Omron CX-Programmer project NuevoProyecto (CX-Programmer 9.51)

# PLC NuevoPLC1: CP1L-E EM

## Global symbols (name address type ; comment)
102.07 BOOL  ; Permis  aspiracio fiser127_8
10.05 BOOL  ; A
220.00 BOOL  ; Alarma 0
220.14 BOOL  ; Alarma batten aspirador
220.15 BOOL  ; Alarma fiser 127_15 aspirador
221.00 BOOL  ; Alarma Fise 127_08 aspirador
T0015 BOOL  ; Temps Acustic per Emmergència
W0.00 BOOL  ; Automatic inici validat
W0.01 BOOL  ; AuxSacBuit
W10.00 BOOL  ; AutomAspirarBatten
W10.01 BOOL  ; AutoAspirarFiser
W10.05 BOOL  ; AutoVibrador
PesApr1500Control D400 CHANNEL  ; d20
PesApr1500ControlXm D401 CHANNEL  ; Celula carga APR  canal de control
PesApr1500ControlY0 D402 CHANNEL  ; Celula carga APR  canal de control
PesApr1500ControlY1 D403 CHANNEL  ; Celula carga APR  canal de control
ScrPesActual D20 INT  ; Valor per la pantalla del pes
ScrPesTarat D22 INT  ; Valor del pes ja tarat
ScrValorMaxPes D24 INT
ScrValorMinPes D23 INT
ScrValorTarat D21 INT  ; Valorque restem al pes real i el passem al tarat
bAutoBattenAigua W10.07 BOOL
bAutoBattenEvAtemp W10.08 BOOL
bAutoBattenEvOli W10.06 BOOL
bAutoFiser127_8Aspir W11.00 BOOL  ; Permis  aspiracio fiser 127_8
bAutoFiserEvAigua W10.10 BOOL
bAutoFiserEvAtemp W10.11 BOOL
bAutoFiserEvOli W10.09 BOOL
bAutoPotRefrigAigua W10.13 BOOL
bAutoPotRefrigAtemp W10.14 BOOL
bAutoPotRefrigOli W10.12 BOOL
bHabBattenEvAigua H8.01 BOOL
bHabBattenEvAtemperador H8.02 BOOL
bHabBattenEvOli H8.00 BOOL
bHabFiserEvAigua H8.04 BOOL
bHabFiserEvAtemperador H8.05 BOOL
bHabFiserEvOli H8.03 BOOL
bHabpotRefrigAigua H8.07 BOOL
bHabpotRefrigAtemp H8.08 BOOL
bHabpotRefrigOli H8.06 BOOL
bManBattenAspir H10.00 BOOL  ; Permis  aspiracio batten
bManBattenEvAigua H10.07 BOOL
bManBattenEvAtemp H10.08 BOOL
bManBattenEvOli H10.06 BOOL
bManFiser127_8Aspir H11.00 BOOL  ; Permis  aspiracio fiser 127_8
bManFiserEvAigua H10.10 BOOL
bManFiserEvAtemp H10.11 BOOL
bManFiserEvOli H10.09 BOOL
bManGranzaVibrador H10.15 BOOL
bManPolsEvBatten127_09 H10.04 BOOL
bManPolsEvFiser127_08 H10.02 BOOL
bManPolsEvFiser127_15 H10.03 BOOL
bManPotRefrigAigua H10.13 BOOL
bManPotRefrigAtemp H10.14 BOOL
bManPotRefrigOli H10.12 BOOL
bManrFiserAspir H10.01 BOOL  ; Permis  aspiracio fiser
bScrBattenAspir 200.00 BOOL  ; Permis  aspiracio batten
bScrBattenEvAigua 200.07 BOOL
bScrBattenEvAtemp 200.08 BOOL
bScrBattenEvOli 200.06 BOOL
bScrFiserAspir 200.01 BOOL  ; Permis  aspiracio fiser
bScrFiserEvAigua 200.10 BOOL
bScrFiserEvAtemp 200.11 BOOL
bScrFiserEvOli 200.09 BOOL
bScrGranzaBaixa 200.05 BOOL
bScrGranzaPujar 200.04 BOOL
bScrGranzaVibrador 200.15 BOOL
bScrPolsEvBatten127_09 203.01 BOOL
bScrPolsEvFiser127_08 200.02 BOOL
bScrPolsEvFiser127_15 200.03 BOOL
bScrPotRefrigAigua 200.13 BOOL
bScrPotRefrigAtemp 200.14 BOOL
bScrPotRefrigOli 200.12 BOOL
inBarrera 1.02 BOOL
inBattenOn 1.00 BOOL
inDetFinalSac 0.06 BOOL
inDetIniciSac 0.07 BOOL
inEVGFiser127_15Tancat 0.03 BOOL
inEmergencia 1.03 BOOL
inEvBatten127_09Obert 1.05 BOOL
inEvBatten127_09Tancat 1.06 BOOL
inEvFiser127_08Obert 0.00 BOOL
inEvFiser127_08Tancat 0.01 BOOL
inEvFiser127_15Obert 0.02 BOOL
inFiserOn 1.01 BOOL
inNivellAspBatten 0.04 BOOL  ; Batten
inNivellAspFiser127_15 0.05 BOOL  ; Fiser
inNivellAspFiser127_8 1.04 BOOL  ; Fiser 127-8
inPolsBaixar 0.10 BOOL
inPolsPujar 0.09 BOOL
inPolsValidarInici 0.11 BOOL
inSelManAuto 0.08 BOOL  ; 0:Auto  1:Man
outBalisa 102.04 BOOL
outBattenAspir 100.00 BOOL  ; Permis  aspiracio batten
outBattenEvAigua 100.07 BOOL
outBattenEvAtemp 101.00 BOOL
outBattenEvOli 100.06 BOOL
outEVGBatten 100.04 BOOL  ; Batten
outEVGFiser127_15 100.05 BOOL  ; Fiser
outEvFiser127_08 102.06 BOOL  ; Fiser 127_8
outFiserAspir 100.01 BOOL  ; Permis  aspiracio fiser
outFiserEvAigua 101.02 BOOL
outFiserEvAtemp 101.03 BOOL
outFiserEvOli 101.01 BOOL
outGranzaBaixa 100.03 BOOL  ; Per baixar el soport del sac hem de fer sortir el pisto
outGranzaPujar 100.02 BOOL  ; per mantenir el sac tensat hem de fer entrar el pisto
outGranzaVibrador 101.07 BOOL
outPotRefrigAigua 101.05 BOOL
outPotRefrigAtemp 101.06 BOOL
outPotRefrigOli 101.04 BOOL
outSemaforGroc 102.01 BOOL
outSemaforSirena 102.03 BOOL
outSemaforVerd 102.00 BOOL
outSemaforVermell 102.02 BOOL
outValidarIniciLed 102.05 BOOL
scrAlarmaDiplay W0.03 BOOL
scrCanviPantalla D11 INT  ; Numero de pantalla a la que es vol anar
scrCanviPantallaComando D10 INT  ; El numero 2 vol dir escriure
scrIconaAlarma W0.02 BOOL
scrPolsTarar 203.00 BOOL

## Program NuevoPrograma1 (cyclic task 0)
Local symbols
f113 BOOL

### Section Manual

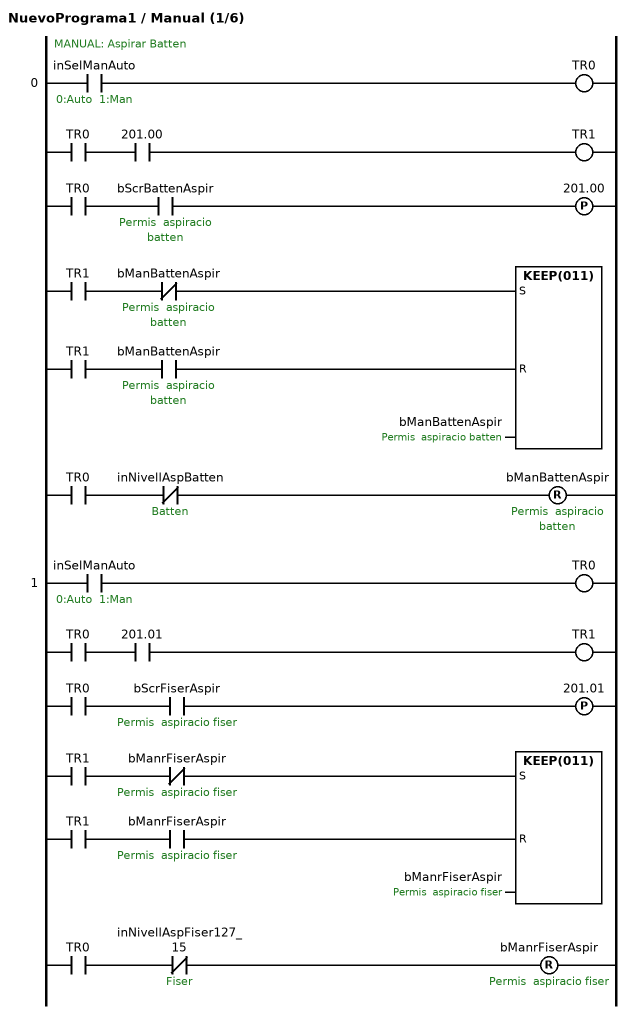
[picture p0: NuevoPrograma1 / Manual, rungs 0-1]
; rung 0: MANUAL: Aspirar Batten
LD inSelManAuto  ; 0:Auto  1:Man
OUT TR0
AND bScrBattenAspir  ; Permis  aspiracio batten
DIFU(013) 201.00
LD TR0
AND 201.00
OUT TR1
ANDNOT bManBattenAspir  ; Permis  aspiracio batten
LD TR1
AND bManBattenAspir  ; Permis  aspiracio batten
KEEP(011) bManBattenAspir  ; Permis  aspiracio batten
LD TR0
ANDNOT inNivellAspBatten  ; Batten
RSET bManBattenAspir  ; Permis  aspiracio batten
; rung 1
LD inSelManAuto  ; 0:Auto  1:Man
OUT TR0
AND bScrFiserAspir  ; Permis  aspiracio fiser
DIFU(013) 201.01
LD TR0
AND 201.01
OUT TR1
ANDNOT bManrFiserAspir  ; Permis  aspiracio fiser
LD TR1
AND bManrFiserAspir  ; Permis  aspiracio fiser
KEEP(011) bManrFiserAspir  ; Permis  aspiracio fiser
LD TR0
ANDNOT inNivellAspFiser127_15  ; Fiser
RSET bManrFiserAspir  ; Permis  aspiracio fiser

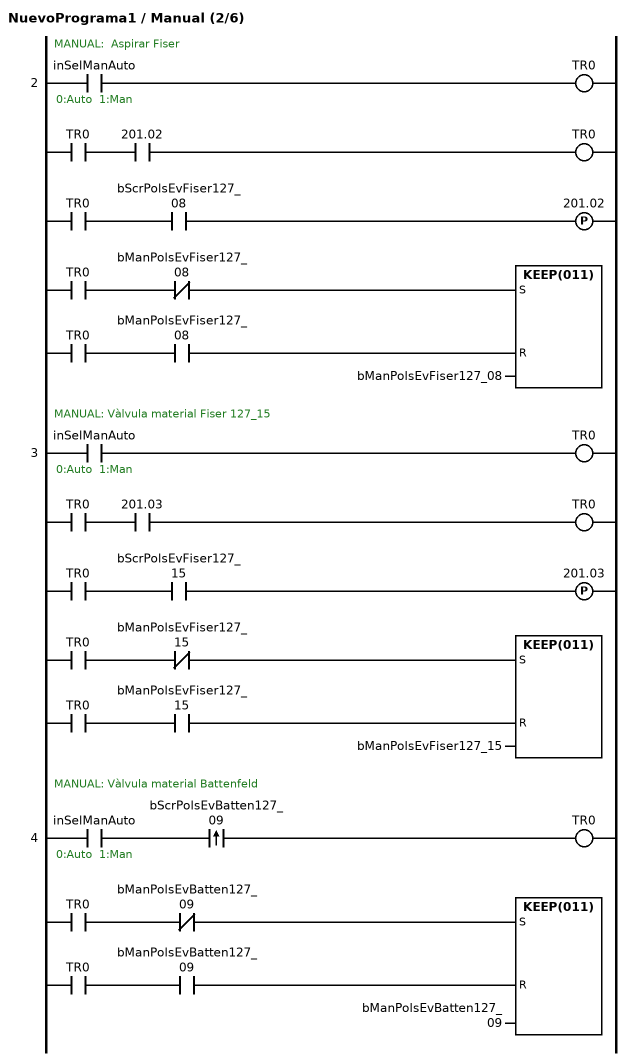
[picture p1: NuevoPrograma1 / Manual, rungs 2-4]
; rung 2: MANUAL:  Aspirar Fiser
LD inSelManAuto  ; 0:Auto  1:Man
OUT TR0
AND bScrPolsEvFiser127_08
DIFU(013) 201.02
LD TR0
AND 201.02
OUT TR0
ANDNOT bManPolsEvFiser127_08
LD TR0
AND bManPolsEvFiser127_08
KEEP(011) bManPolsEvFiser127_08
; rung 3: MANUAL: Vàlvula material Fiser 127_15
LD inSelManAuto  ; 0:Auto  1:Man
OUT TR0
AND bScrPolsEvFiser127_15
DIFU(013) 201.03
LD TR0
AND 201.03
OUT TR0
ANDNOT bManPolsEvFiser127_15
LD TR0
AND bManPolsEvFiser127_15
KEEP(011) bManPolsEvFiser127_15
; rung 4: MANUAL: Vàlvula material Battenfeld
LD inSelManAuto  ; 0:Auto  1:Man
@AND bScrPolsEvBatten127_09
OUT TR0
ANDNOT bManPolsEvBatten127_09
LD TR0
AND bManPolsEvBatten127_09
KEEP(011) bManPolsEvBatten127_09

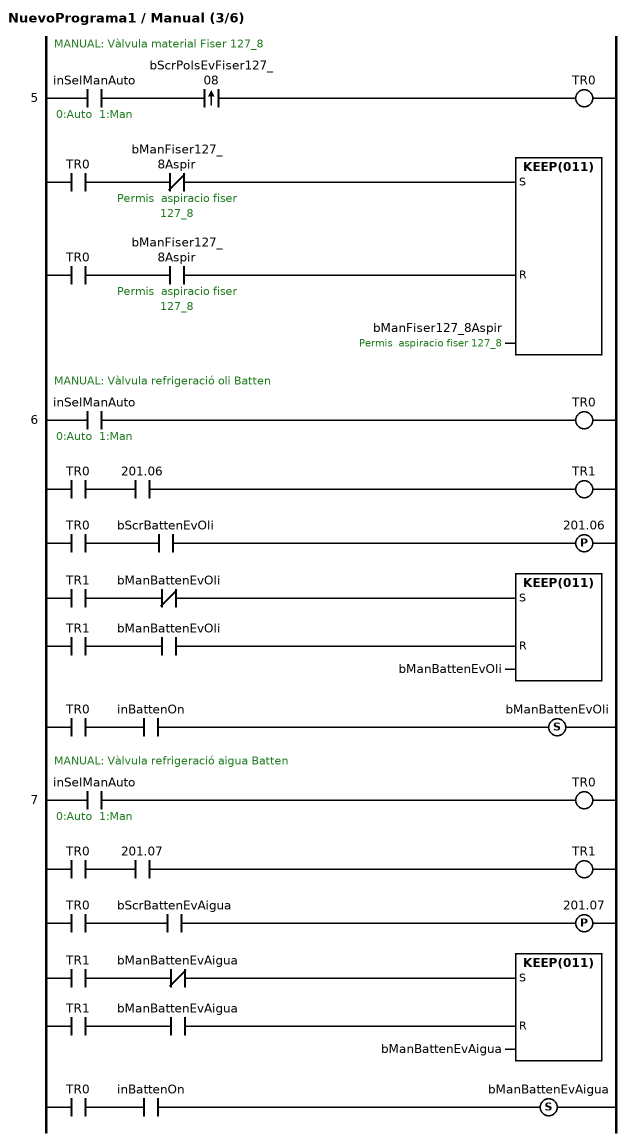
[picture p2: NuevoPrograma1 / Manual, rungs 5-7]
; rung 5: MANUAL: Vàlvula material Fiser 127_8
LD inSelManAuto  ; 0:Auto  1:Man
@AND bScrPolsEvFiser127_08
OUT TR0
ANDNOT bManFiser127_8Aspir  ; Permis  aspiracio fiser 127_8
LD TR0
AND bManFiser127_8Aspir  ; Permis  aspiracio fiser 127_8
KEEP(011) bManFiser127_8Aspir  ; Permis  aspiracio fiser 127_8
; rung 6: MANUAL: Vàlvula refrigeració oli Batten
LD inSelManAuto  ; 0:Auto  1:Man
OUT TR0
AND bScrBattenEvOli
DIFU(013) 201.06
LD TR0
AND 201.06
OUT TR1
ANDNOT bManBattenEvOli
LD TR1
AND bManBattenEvOli
KEEP(011) bManBattenEvOli
LD TR0
AND inBattenOn
SET bManBattenEvOli
; rung 7: MANUAL: Vàlvula refrigeració aigua Batten
LD inSelManAuto  ; 0:Auto  1:Man
OUT TR0
AND bScrBattenEvAigua
DIFU(013) 201.07
LD TR0
AND 201.07
OUT TR1
ANDNOT bManBattenEvAigua
LD TR1
AND bManBattenEvAigua
KEEP(011) bManBattenEvAigua
LD TR0
AND inBattenOn
SET bManBattenEvAigua

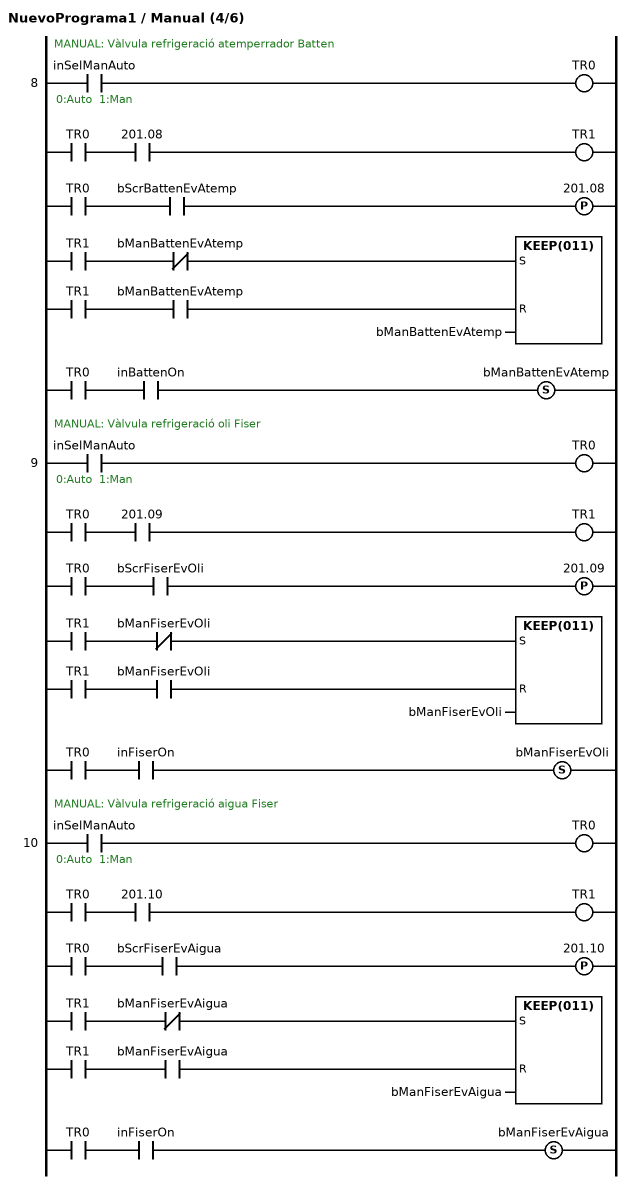
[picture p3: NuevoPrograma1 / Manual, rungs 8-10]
; rung 8: MANUAL: Vàlvula refrigeració atemperrador Batten
LD inSelManAuto  ; 0:Auto  1:Man
OUT TR0
AND bScrBattenEvAtemp
DIFU(013) 201.08
LD TR0
AND 201.08
OUT TR1
ANDNOT bManBattenEvAtemp
LD TR1
AND bManBattenEvAtemp
KEEP(011) bManBattenEvAtemp
LD TR0
AND inBattenOn
SET bManBattenEvAtemp
; rung 9: MANUAL: Vàlvula refrigeració oli Fiser
LD inSelManAuto  ; 0:Auto  1:Man
OUT TR0
AND bScrFiserEvOli
DIFU(013) 201.09
LD TR0
AND 201.09
OUT TR1
ANDNOT bManFiserEvOli
LD TR1
AND bManFiserEvOli
KEEP(011) bManFiserEvOli
LD TR0
AND inFiserOn
SET bManFiserEvOli
; rung 10: MANUAL: Vàlvula refrigeració aigua Fiser
LD inSelManAuto  ; 0:Auto  1:Man
OUT TR0
AND bScrFiserEvAigua
DIFU(013) 201.10
LD TR0
AND 201.10
OUT TR1
ANDNOT bManFiserEvAigua
LD TR1
AND bManFiserEvAigua
KEEP(011) bManFiserEvAigua
LD TR0
AND inFiserOn
SET bManFiserEvAigua

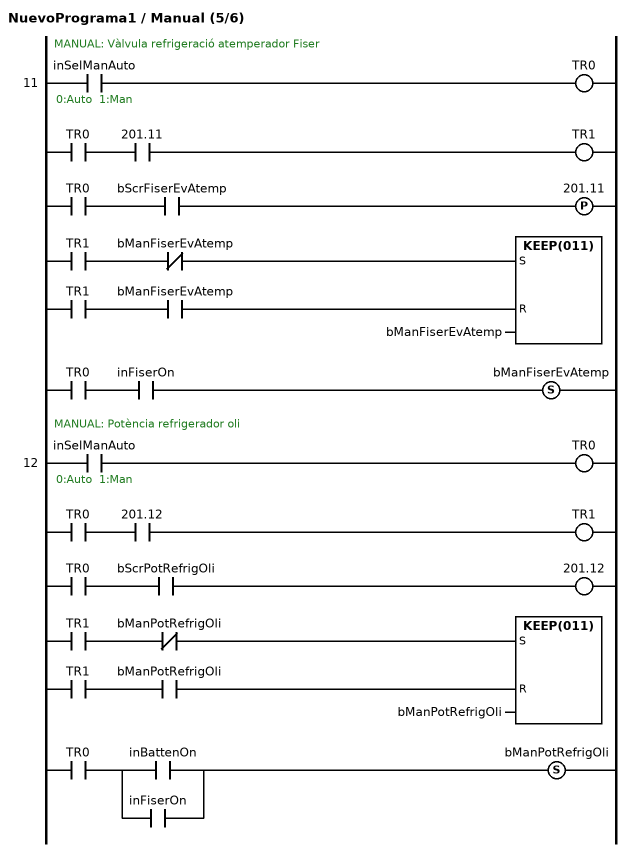
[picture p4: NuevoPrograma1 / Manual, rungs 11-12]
; rung 11: MANUAL: Vàlvula refrigeració atemperador Fiser
LD inSelManAuto  ; 0:Auto  1:Man
OUT TR0
AND bScrFiserEvAtemp
DIFU(013) 201.11
LD TR0
AND 201.11
OUT TR1
ANDNOT bManFiserEvAtemp
LD TR1
AND bManFiserEvAtemp
KEEP(011) bManFiserEvAtemp
LD TR0
AND inFiserOn
SET bManFiserEvAtemp
; rung 12: MANUAL: Potència refrigerador oli
LD inSelManAuto  ; 0:Auto  1:Man
OUT TR0
AND bScrPotRefrigOli
OUT 201.12
LD TR0
AND 201.12
OUT TR1
ANDNOT bManPotRefrigOli
LD TR1
AND bManPotRefrigOli
KEEP(011) bManPotRefrigOli
LD TR0
LD inBattenOn
OR inFiserOn
ANDLD
SET bManPotRefrigOli

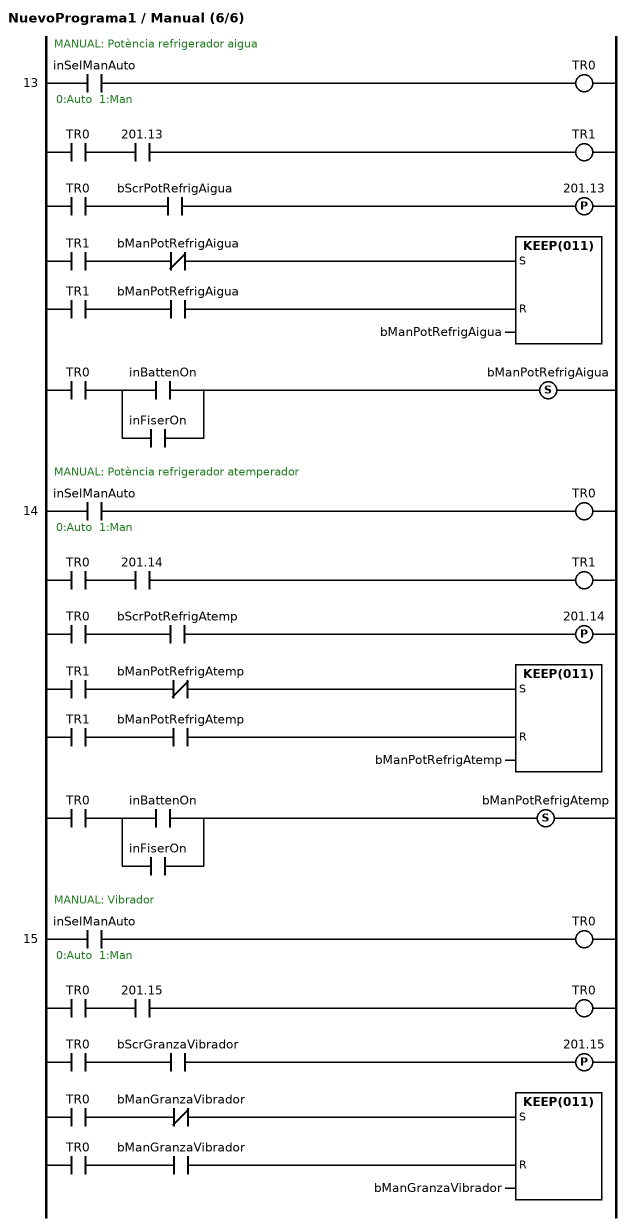
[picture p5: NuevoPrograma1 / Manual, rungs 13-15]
; rung 13: MANUAL: Potència refrigerador aigua
LD inSelManAuto  ; 0:Auto  1:Man
OUT TR0
AND bScrPotRefrigAigua
DIFU(013) 201.13
LD TR0
AND 201.13
OUT TR1
ANDNOT bManPotRefrigAigua
LD TR1
AND bManPotRefrigAigua
KEEP(011) bManPotRefrigAigua
LD TR0
LD inBattenOn
OR inFiserOn
ANDLD
SET bManPotRefrigAigua
; rung 14: MANUAL: Potència refrigerador atemperador
LD inSelManAuto  ; 0:Auto  1:Man
OUT TR0
AND bScrPotRefrigAtemp
DIFU(013) 201.14
LD TR0
AND 201.14
OUT TR1
ANDNOT bManPotRefrigAtemp
LD TR1
AND bManPotRefrigAtemp
KEEP(011) bManPotRefrigAtemp
LD TR0
LD inBattenOn
OR inFiserOn
ANDLD
SET bManPotRefrigAtemp
; rung 15: MANUAL: Vibrador
LD inSelManAuto  ; 0:Auto  1:Man
OUT TR0
AND bScrGranzaVibrador
DIFU(013) 201.15
LD TR0
AND 201.15
OUT TR0
ANDNOT bManGranzaVibrador
LD TR0
AND bManGranzaVibrador
KEEP(011) bManGranzaVibrador

### Section Automatic

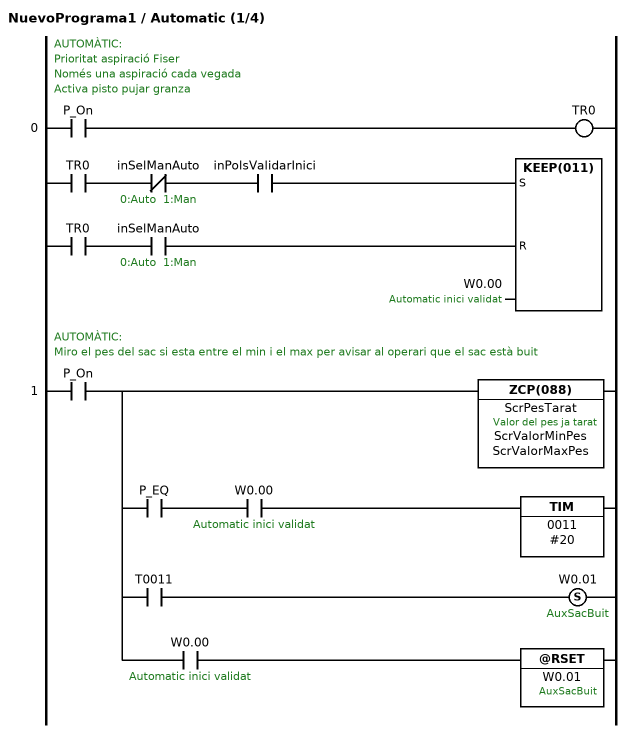
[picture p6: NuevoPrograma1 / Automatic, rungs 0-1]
; rung 0: AUTOMÀTIC: / Prioritat aspiració Fiser / Només una aspiració cada vegada / Activa pisto pujar granza
LD P_On
OUT TR0
ANDNOT inSelManAuto  ; 0:Auto  1:Man
AND inPolsValidarInici
LD TR0
AND inSelManAuto  ; 0:Auto  1:Man
KEEP(011) W0.00  ; Automatic inici validat
; rung 1: AUTOMÀTIC: / Miro el pes del sac si esta entre el min i el max per avisar al operari que el sac està buit
LD P_On
OUT TR0
ZCP(088) ScrPesTarat ScrValorMinPes ScrValorMaxPes  ; Valor del pes ja tarat
AND P_EQ
AND W0.00  ; Automatic inici validat
TIM 0011 #20
LD TR0
AND T0011
SET W0.01  ; AuxSacBuit
LD TR0
AND W0.00  ; Automatic inici validat
@RSET W0.01  ; AuxSacBuit

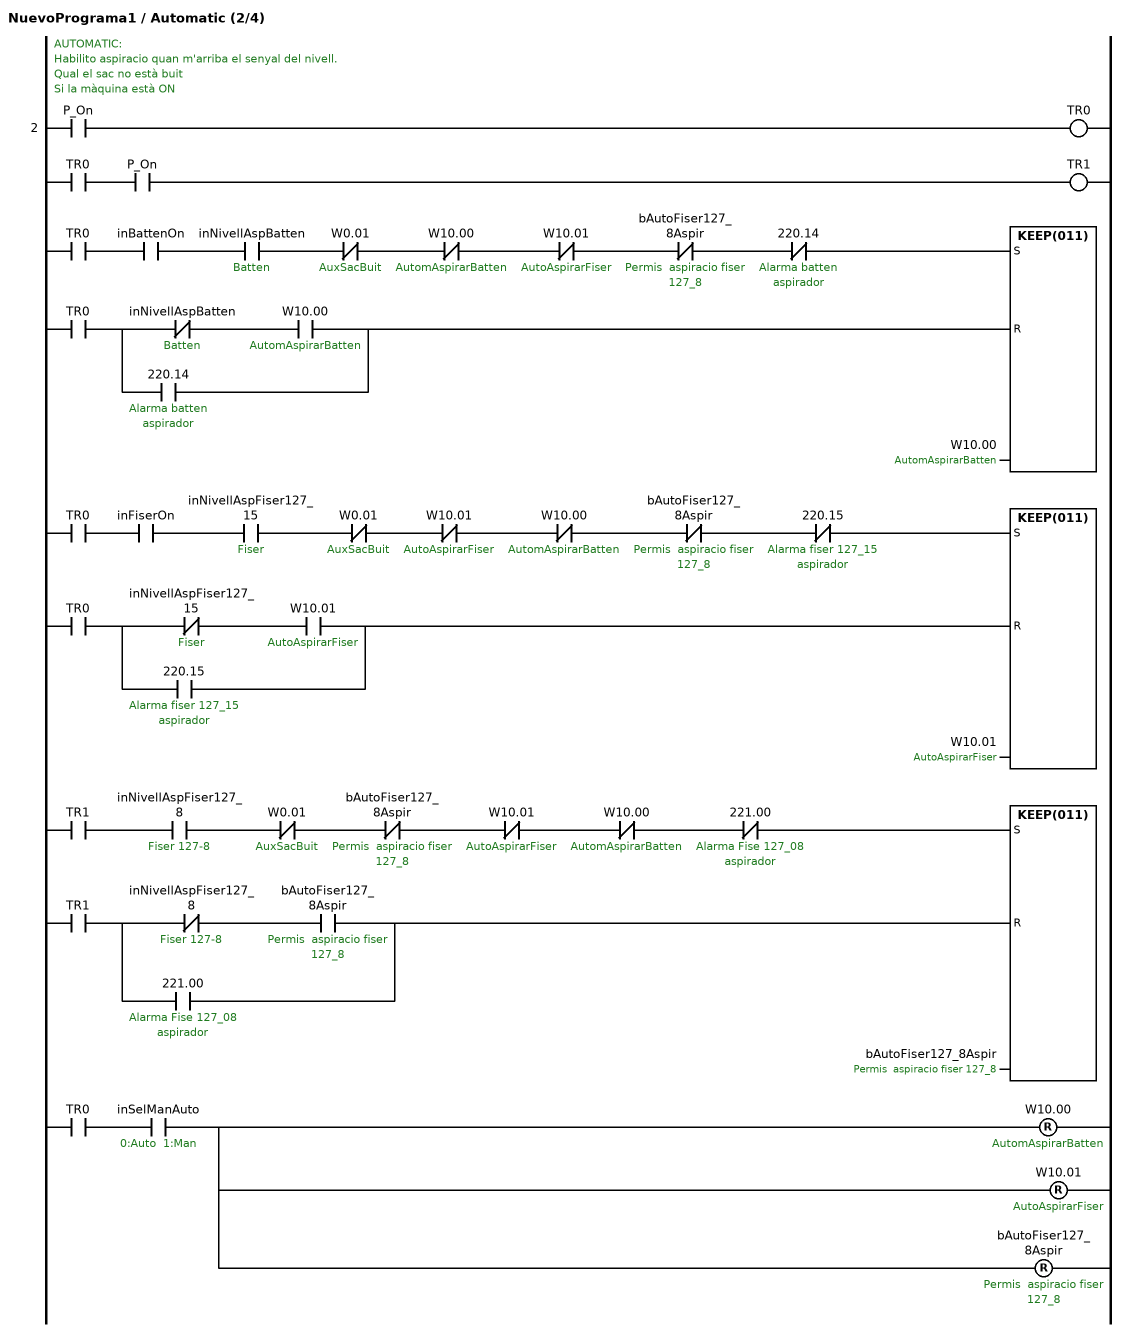
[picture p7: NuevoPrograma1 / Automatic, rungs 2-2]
; rung 2: AUTOMATIC: / Habilito aspiracio quan m'arriba el senyal del nivell. / Qual el sac no està buit / Si la màquina està ON
LD P_On
OUT TR0
AND inBattenOn
AND inNivellAspBatten  ; Batten
ANDNOT W0.01  ; AuxSacBuit
ANDNOT W10.00  ; AutomAspirarBatten
ANDNOT W10.01  ; AutoAspirarFiser
ANDNOT bAutoFiser127_8Aspir  ; Permis  aspiracio fiser 127_8
ANDNOT 220.14  ; Alarma batten aspirador
LD TR0
LDNOT inNivellAspBatten  ; Batten
AND W10.00  ; AutomAspirarBatten
OR 220.14  ; Alarma batten aspirador
ANDLD
KEEP(011) W10.00  ; AutomAspirarBatten
LD TR0
AND inFiserOn
AND inNivellAspFiser127_15  ; Fiser
ANDNOT W0.01  ; AuxSacBuit
ANDNOT W10.01  ; AutoAspirarFiser
ANDNOT W10.00  ; AutomAspirarBatten
ANDNOT bAutoFiser127_8Aspir  ; Permis  aspiracio fiser 127_8
ANDNOT 220.15  ; Alarma fiser 127_15 aspirador
LD TR0
LDNOT inNivellAspFiser127_15  ; Fiser
AND W10.01  ; AutoAspirarFiser
OR 220.15  ; Alarma fiser 127_15 aspirador
ANDLD
KEEP(011) W10.01  ; AutoAspirarFiser
LD TR0
AND P_On
OUT TR1
AND inNivellAspFiser127_8  ; Fiser 127-8
ANDNOT W0.01  ; AuxSacBuit
ANDNOT bAutoFiser127_8Aspir  ; Permis  aspiracio fiser 127_8
ANDNOT W10.01  ; AutoAspirarFiser
ANDNOT W10.00  ; AutomAspirarBatten
ANDNOT 221.00  ; Alarma Fise 127_08 aspirador
LD TR1
LDNOT inNivellAspFiser127_8  ; Fiser 127-8
AND bAutoFiser127_8Aspir  ; Permis  aspiracio fiser 127_8
OR 221.00  ; Alarma Fise 127_08 aspirador
ANDLD
KEEP(011) bAutoFiser127_8Aspir  ; Permis  aspiracio fiser 127_8
LD TR0
AND inSelManAuto  ; 0:Auto  1:Man
RSET W10.00  ; AutomAspirarBatten
RSET W10.01  ; AutoAspirarFiser
RSET bAutoFiser127_8Aspir  ; Permis  aspiracio fiser 127_8

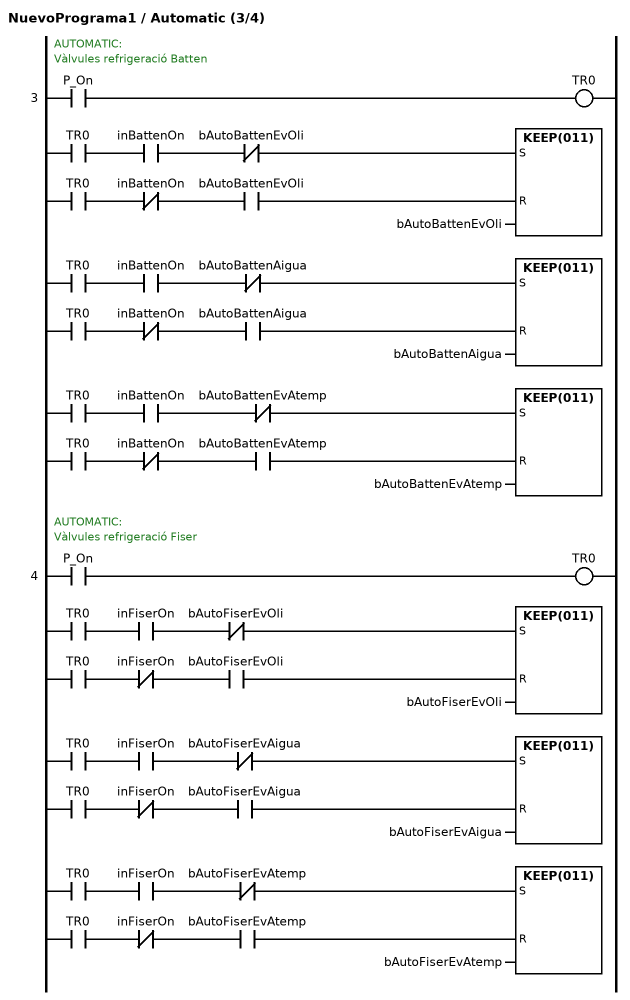
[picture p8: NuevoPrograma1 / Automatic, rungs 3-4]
; rung 3: AUTOMATIC: / Vàlvules refrigeració Batten
LD P_On
OUT TR0
AND inBattenOn
ANDNOT bAutoBattenEvOli
LD TR0
ANDNOT inBattenOn
AND bAutoBattenEvOli
KEEP(011) bAutoBattenEvOli
LD TR0
AND inBattenOn
ANDNOT bAutoBattenAigua
LD TR0
ANDNOT inBattenOn
AND bAutoBattenAigua
KEEP(011) bAutoBattenAigua
LD TR0
AND inBattenOn
ANDNOT bAutoBattenEvAtemp
LD TR0
ANDNOT inBattenOn
AND bAutoBattenEvAtemp
KEEP(011) bAutoBattenEvAtemp
; rung 4: AUTOMATIC: / Vàlvules refrigeració Fiser
LD P_On
OUT TR0
AND inFiserOn
ANDNOT bAutoFiserEvOli
LD TR0
ANDNOT inFiserOn
AND bAutoFiserEvOli
KEEP(011) bAutoFiserEvOli
LD TR0
AND inFiserOn
ANDNOT bAutoFiserEvAigua
LD TR0
ANDNOT inFiserOn
AND bAutoFiserEvAigua
KEEP(011) bAutoFiserEvAigua
LD TR0
AND inFiserOn
ANDNOT bAutoFiserEvAtemp
LD TR0
ANDNOT inFiserOn
AND bAutoFiserEvAtemp
KEEP(011) bAutoFiserEvAtemp

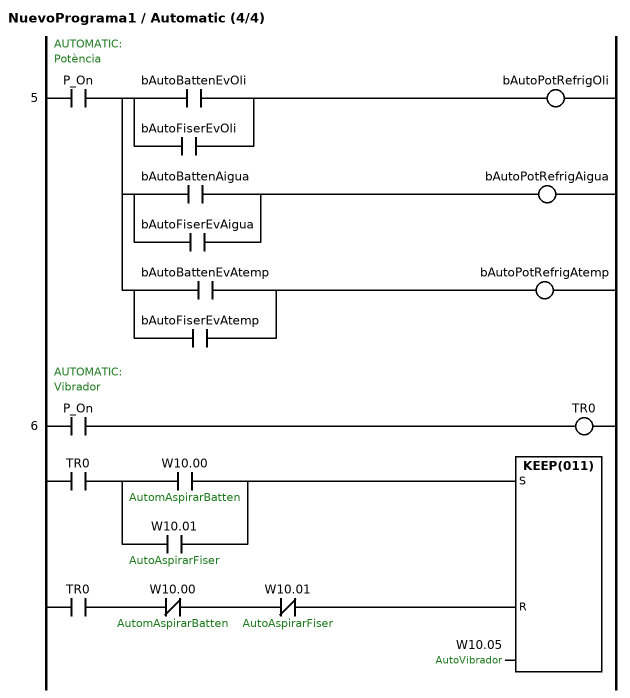
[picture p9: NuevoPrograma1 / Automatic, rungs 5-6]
; rung 5: AUTOMATIC: / Potència
LD P_On
OUT TR0
LD bAutoBattenEvOli
OR bAutoFiserEvOli
ANDLD
OUT bAutoPotRefrigOli
LD TR0
LD bAutoBattenAigua
OR bAutoFiserEvAigua
ANDLD
OUT bAutoPotRefrigAigua
LD TR0
LD bAutoBattenEvAtemp
OR bAutoFiserEvAtemp
ANDLD
OUT bAutoPotRefrigAtemp
; rung 6: AUTOMATIC: / Vibrador
LD P_On
OUT TR0
LD W10.00  ; AutomAspirarBatten
OR W10.01  ; AutoAspirarFiser
ANDLD
LD TR0
ANDNOT W10.00  ; AutomAspirarBatten
ANDNOT W10.01  ; AutoAspirarFiser
KEEP(011) W10.05  ; AutoVibrador

### Section AnalogicaPes

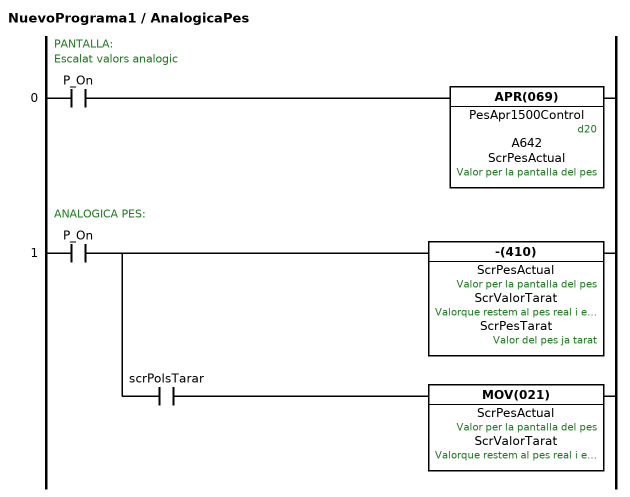
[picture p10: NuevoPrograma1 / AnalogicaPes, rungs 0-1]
; rung 0: PANTALLA: / Escalat valors analogic
LD P_On
APR(069) PesApr1500Control A642 ScrPesActual  ; d20, Valor per la pantalla del pes
; rung 1: ANALOGICA PES:
LD P_On
-(410) ScrPesActual ScrValorTarat ScrPesTarat  ; Valor per la pantalla del pes, Valorque restem al pes real i el passem al tarat, Valor del pes ja tarat
AND scrPolsTarar
MOV(021) ScrPesActual ScrValorTarat  ; Valor per la pantalla del pes, Valorque restem al pes real i el passem al tarat

### Section Sortides

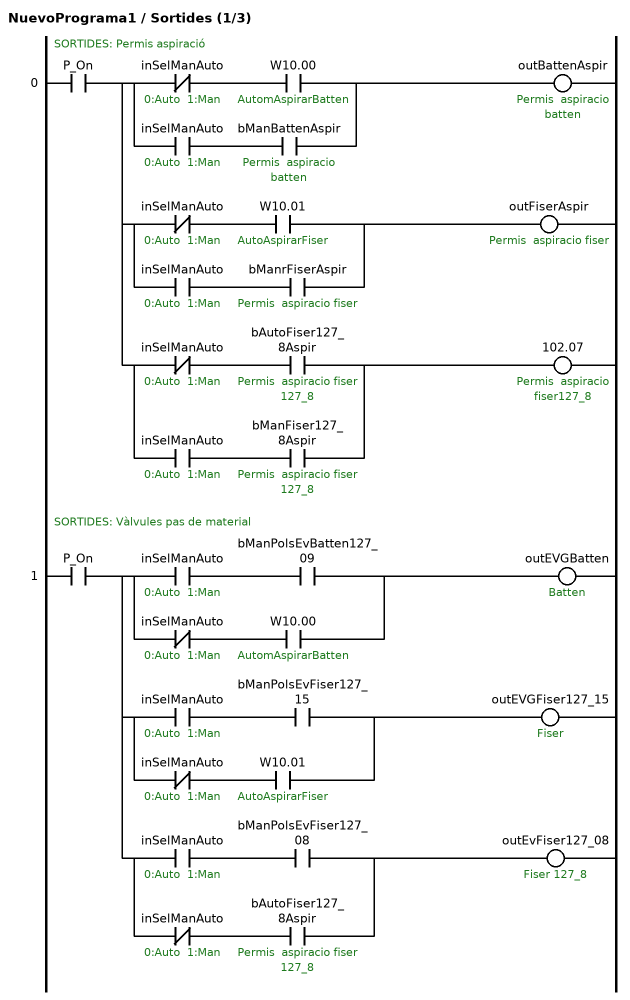
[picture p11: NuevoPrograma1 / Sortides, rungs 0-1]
; rung 0: SORTIDES: Permis aspiració
LD P_On
OUT TR0
LDNOT inSelManAuto  ; 0:Auto  1:Man
AND W10.00  ; AutomAspirarBatten
LD inSelManAuto  ; 0:Auto  1:Man
AND bManBattenAspir  ; Permis  aspiracio batten
ORLD
ANDLD
OUT outBattenAspir  ; Permis  aspiracio batten
LD TR0
LDNOT inSelManAuto  ; 0:Auto  1:Man
AND W10.01  ; AutoAspirarFiser
LD inSelManAuto  ; 0:Auto  1:Man
AND bManrFiserAspir  ; Permis  aspiracio fiser
ORLD
ANDLD
OUT outFiserAspir  ; Permis  aspiracio fiser
LD TR0
LDNOT inSelManAuto  ; 0:Auto  1:Man
AND bAutoFiser127_8Aspir  ; Permis  aspiracio fiser 127_8
LD inSelManAuto  ; 0:Auto  1:Man
AND bManFiser127_8Aspir  ; Permis  aspiracio fiser 127_8
ORLD
ANDLD
OUT 102.07  ; Permis  aspiracio fiser127_8
; rung 1: SORTIDES: Vàlvules pas de material
LD P_On
OUT TR0
LD inSelManAuto  ; 0:Auto  1:Man
AND bManPolsEvBatten127_09
LDNOT inSelManAuto  ; 0:Auto  1:Man
AND W10.00  ; AutomAspirarBatten
ORLD
ANDLD
OUT outEVGBatten  ; Batten
LD TR0
LD inSelManAuto  ; 0:Auto  1:Man
AND bManPolsEvFiser127_15
LDNOT inSelManAuto  ; 0:Auto  1:Man
AND W10.01  ; AutoAspirarFiser
ORLD
ANDLD
OUT outEVGFiser127_15  ; Fiser
LD TR0
LD inSelManAuto  ; 0:Auto  1:Man
AND bManPolsEvFiser127_08
LDNOT inSelManAuto  ; 0:Auto  1:Man
AND bAutoFiser127_8Aspir  ; Permis  aspiracio fiser 127_8
ORLD
ANDLD
OUT outEvFiser127_08  ; Fiser 127_8

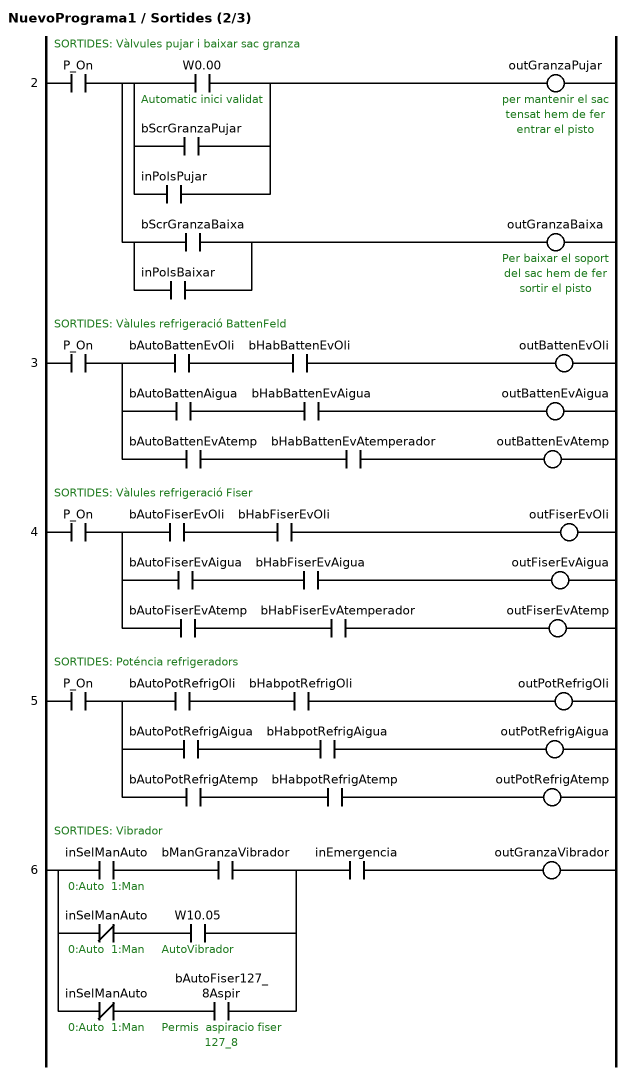
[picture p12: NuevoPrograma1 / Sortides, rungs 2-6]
; rung 2: SORTIDES: Vàlvules pujar i baixar sac granza
LD P_On
OUT TR0
LD W0.00  ; Automatic inici validat
OR bScrGranzaPujar
OR inPolsPujar
ANDLD
OUT outGranzaPujar  ; per mantenir el sac tensat hem de fer entrar el pisto
LD TR0
LD bScrGranzaBaixa
OR inPolsBaixar
ANDLD
OUT outGranzaBaixa  ; Per baixar el soport del sac hem de fer sortir el pisto
; rung 3: SORTIDES: Vàlules refrigeració BattenFeld
LD P_On
OUT TR0
AND bAutoBattenEvOli
AND bHabBattenEvOli
OUT outBattenEvOli
LD TR0
AND bAutoBattenAigua
AND bHabBattenEvAigua
OUT outBattenEvAigua
LD TR0
AND bAutoBattenEvAtemp
AND bHabBattenEvAtemperador
OUT outBattenEvAtemp
; rung 4: SORTIDES: Vàlules refrigeració Fiser
LD P_On
OUT TR0
AND bAutoFiserEvOli
AND bHabFiserEvOli
OUT outFiserEvOli
LD TR0
AND bAutoFiserEvAigua
AND bHabFiserEvAigua
OUT outFiserEvAigua
LD TR0
AND bAutoFiserEvAtemp
AND bHabFiserEvAtemperador
OUT outFiserEvAtemp
; rung 5: SORTIDES: Poténcia refrigeradors
LD P_On
OUT TR0
AND bAutoPotRefrigOli
AND bHabpotRefrigOli
OUT outPotRefrigOli
LD TR0
AND bAutoPotRefrigAigua
AND bHabpotRefrigAigua
OUT outPotRefrigAigua
LD TR0
AND bAutoPotRefrigAtemp
AND bHabpotRefrigAtemp
OUT outPotRefrigAtemp
; rung 6: SORTIDES: Vibrador
LD inSelManAuto  ; 0:Auto  1:Man
AND bManGranzaVibrador
LDNOT inSelManAuto  ; 0:Auto  1:Man
AND W10.05  ; AutoVibrador
ORLD
LDNOT inSelManAuto  ; 0:Auto  1:Man
AND bAutoFiser127_8Aspir  ; Permis  aspiracio fiser 127_8
ORLD
AND inEmergencia
OUT outGranzaVibrador

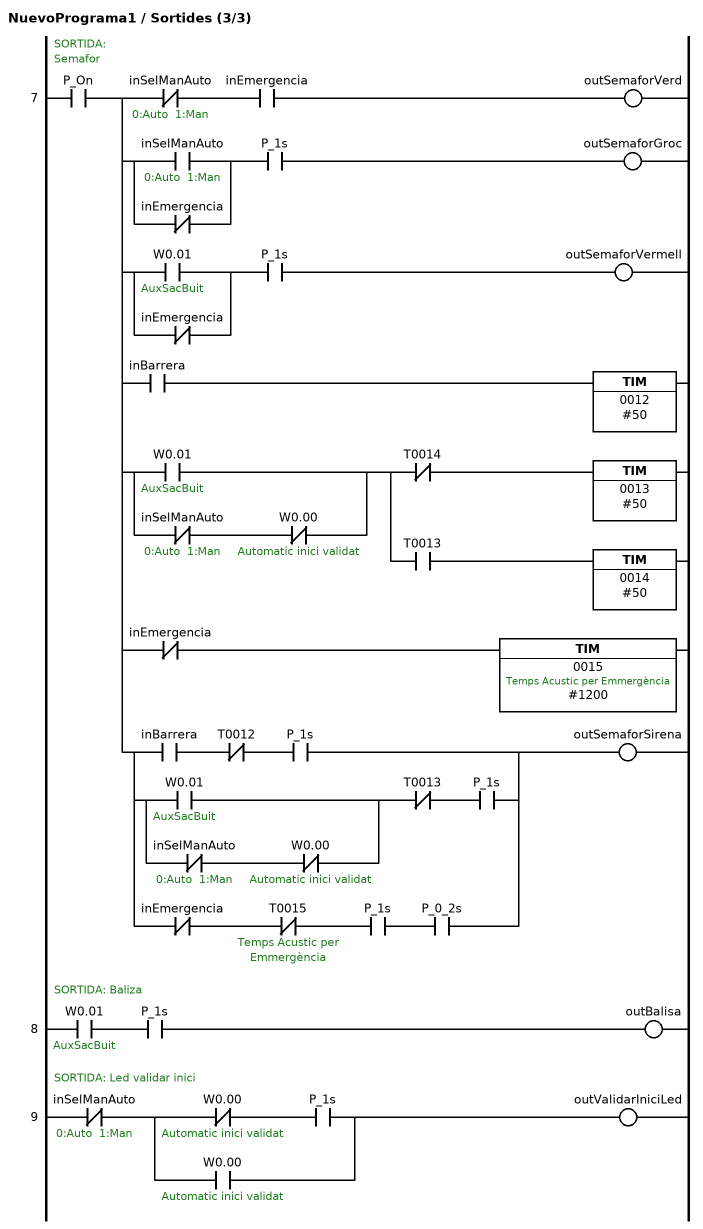
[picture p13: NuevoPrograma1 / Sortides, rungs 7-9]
; rung 7: SORTIDA: / Semafor
LD P_On
OUT TR0
ANDNOT inSelManAuto  ; 0:Auto  1:Man
AND inEmergencia
OUT outSemaforVerd
LD TR0
LD inSelManAuto  ; 0:Auto  1:Man
ORNOT inEmergencia
ANDLD
AND P_1s
OUT outSemaforGroc
LD TR0
LD W0.01  ; AuxSacBuit
ORNOT inEmergencia
ANDLD
AND P_1s
OUT outSemaforVermell
LD TR0
AND inBarrera
TIM 0012 #50
LD TR0
LD W0.01  ; AuxSacBuit
LDNOT inSelManAuto  ; 0:Auto  1:Man
ANDNOT W0.00  ; Automatic inici validat
ORLD
ANDLD
OUT TR1
ANDNOT T0014
TIM 0013 #50
LD TR1
AND T0013
TIM 0014 #50
LD TR0
ANDNOT inEmergencia
TIM 0015 #1200  ; Temps Acustic per Emmergència
LD TR0
LD inBarrera
ANDNOT T0012
AND P_1s
LD W0.01  ; AuxSacBuit
LDNOT inSelManAuto  ; 0:Auto  1:Man
ANDNOT W0.00  ; Automatic inici validat
ORLD
ANDNOT T0013
AND P_1s
ORLD
LDNOT inEmergencia
ANDNOT T0015  ; Temps Acustic per Emmergència
AND P_1s
AND P_0_2s
ORLD
ANDLD
OUT outSemaforSirena
; rung 8: SORTIDA: Baliza
LD W0.01  ; AuxSacBuit
AND P_1s
OUT outBalisa
; rung 9: SORTIDA: Led validar inici
LDNOT inSelManAuto  ; 0:Auto  1:Man
LDNOT W0.00  ; Automatic inici validat
AND P_1s
OR W0.00  ; Automatic inici validat
ANDLD
OUT outValidarIniciLed

### Section Pantalla

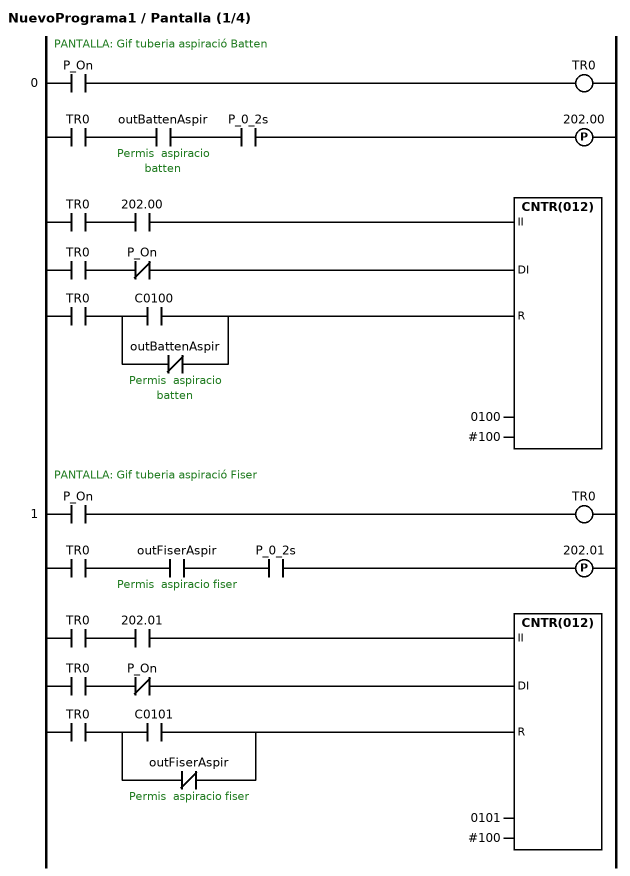
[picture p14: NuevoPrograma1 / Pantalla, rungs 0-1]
; rung 0: PANTALLA: Gif tuberia aspiració Batten
LD P_On
OUT TR0
AND outBattenAspir  ; Permis  aspiracio batten
AND P_0_2s
DIFU(013) 202.00
LD TR0
AND 202.00
LD TR0
ANDNOT P_On
LD TR0
LD C0100
ORNOT outBattenAspir  ; Permis  aspiracio batten
ANDLD
CNTR(012) 0100 #100
; rung 1: PANTALLA: Gif tuberia aspiració Fiser
LD P_On
OUT TR0
AND outFiserAspir  ; Permis  aspiracio fiser
AND P_0_2s
DIFU(013) 202.01
LD TR0
AND 202.01
LD TR0
ANDNOT P_On
LD TR0
LD C0101
ORNOT outFiserAspir  ; Permis  aspiracio fiser
ANDLD
CNTR(012) 0101 #100

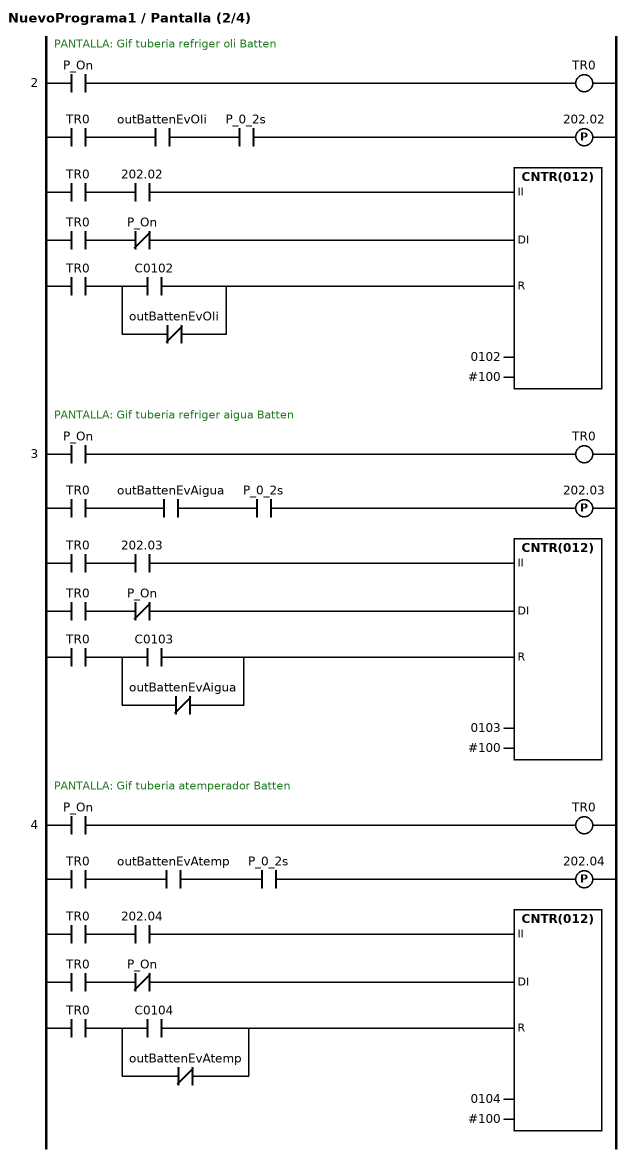
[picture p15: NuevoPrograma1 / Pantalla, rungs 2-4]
; rung 2: PANTALLA: Gif tuberia refriger oli Batten
LD P_On
OUT TR0
AND outBattenEvOli
AND P_0_2s
DIFU(013) 202.02
LD TR0
AND 202.02
LD TR0
ANDNOT P_On
LD TR0
LD C0102
ORNOT outBattenEvOli
ANDLD
CNTR(012) 0102 #100
; rung 3: PANTALLA: Gif tuberia refriger aigua Batten
LD P_On
OUT TR0
AND outBattenEvAigua
AND P_0_2s
DIFU(013) 202.03
LD TR0
AND 202.03
LD TR0
ANDNOT P_On
LD TR0
LD C0103
ORNOT outBattenEvAigua
ANDLD
CNTR(012) 0103 #100
; rung 4: PANTALLA: Gif tuberia atemperador Batten
LD P_On
OUT TR0
AND outBattenEvAtemp
AND P_0_2s
DIFU(013) 202.04
LD TR0
AND 202.04
LD TR0
ANDNOT P_On
LD TR0
LD C0104
ORNOT outBattenEvAtemp
ANDLD
CNTR(012) 0104 #100

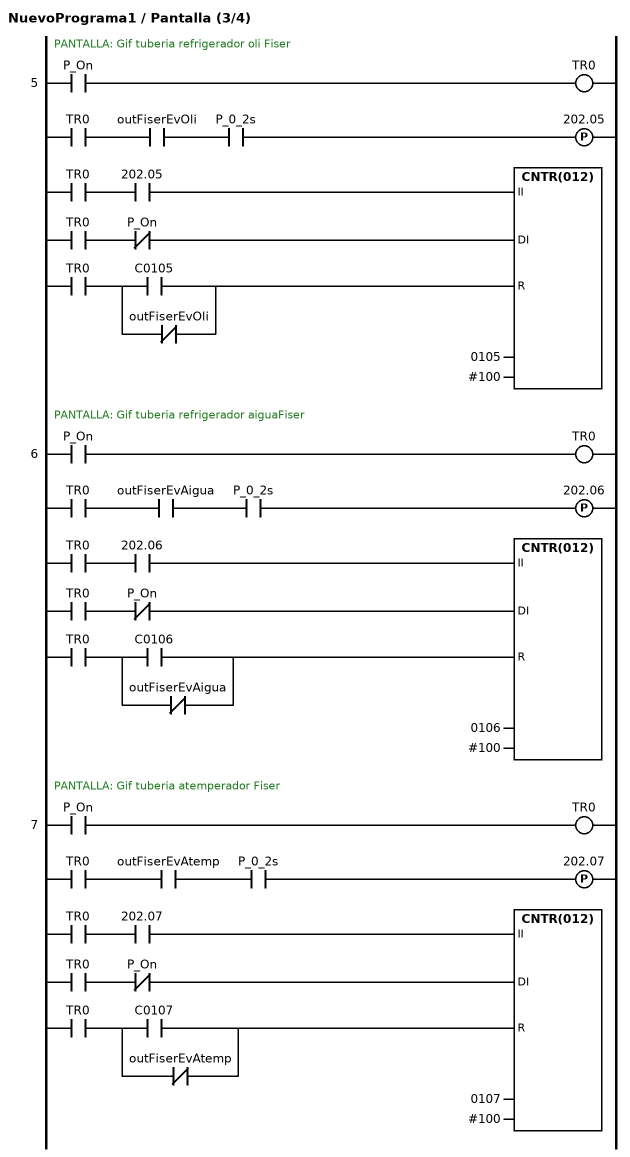
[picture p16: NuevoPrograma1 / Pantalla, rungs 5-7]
; rung 5: PANTALLA: Gif tuberia refrigerador oli Fiser
LD P_On
OUT TR0
AND outFiserEvOli
AND P_0_2s
DIFU(013) 202.05
LD TR0
AND 202.05
LD TR0
ANDNOT P_On
LD TR0
LD C0105
ORNOT outFiserEvOli
ANDLD
CNTR(012) 0105 #100
; rung 6: PANTALLA: Gif tuberia refrigerador aiguaFiser
LD P_On
OUT TR0
AND outFiserEvAigua
AND P_0_2s
DIFU(013) 202.06
LD TR0
AND 202.06
LD TR0
ANDNOT P_On
LD TR0
LD C0106
ORNOT outFiserEvAigua
ANDLD
CNTR(012) 0106 #100
; rung 7: PANTALLA: Gif tuberia atemperador Fiser
LD P_On
OUT TR0
AND outFiserEvAtemp
AND P_0_2s
DIFU(013) 202.07
LD TR0
AND 202.07
LD TR0
ANDNOT P_On
LD TR0
LD C0107
ORNOT outFiserEvAtemp
ANDLD
CNTR(012) 0107 #100

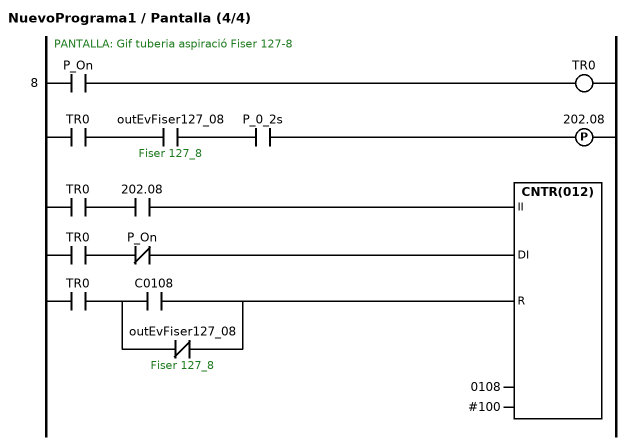
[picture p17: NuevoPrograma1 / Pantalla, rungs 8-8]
; rung 8: PANTALLA: Gif tuberia aspiració Fiser 127-8
LD P_On
OUT TR0
AND outEvFiser127_08  ; Fiser 127_8
AND P_0_2s
DIFU(013) 202.08
LD TR0
AND 202.08
LD TR0
ANDNOT P_On
LD TR0
LD C0108
ORNOT outEvFiser127_08  ; Fiser 127_8
ANDLD
CNTR(012) 0108 #100

### Section Alarmes

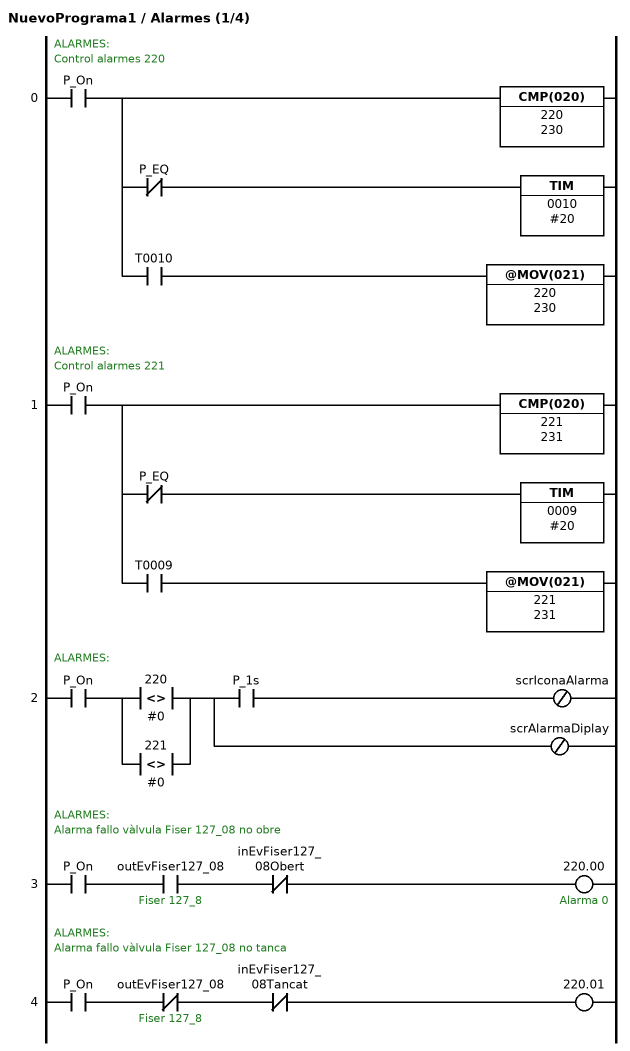
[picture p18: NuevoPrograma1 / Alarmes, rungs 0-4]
; rung 0: ALARMES: / Control alarmes 220
LD P_On
OUT TR0
CMP(020) 220 230
ANDNOT P_EQ
TIM 0010 #20
LD TR0
AND T0010
@MOV(021) 220 230
; rung 1: ALARMES: / Control alarmes 221
LD P_On
OUT TR0
CMP(020) 221 231
ANDNOT P_EQ
TIM 0009 #20
LD TR0
AND T0009
@MOV(021) 221 231
; rung 2: ALARMES:
LD P_On
LD<>(305) 220 #0
OR<>(305) 221 #0
ANDLD
OUT TR0
AND P_1s
OUTNOT scrIconaAlarma
LD TR0
OUTNOT scrAlarmaDiplay
; rung 3: ALARMES: / Alarma fallo vàlvula Fiser 127_08 no obre
LD P_On
AND outEvFiser127_08  ; Fiser 127_8
ANDNOT inEvFiser127_08Obert
OUT 220.00  ; Alarma 0
; rung 4: ALARMES: / Alarma fallo vàlvula Fiser 127_08 no tanca
LD P_On
ANDNOT outEvFiser127_08  ; Fiser 127_8
ANDNOT inEvFiser127_08Tancat
OUT 220.01

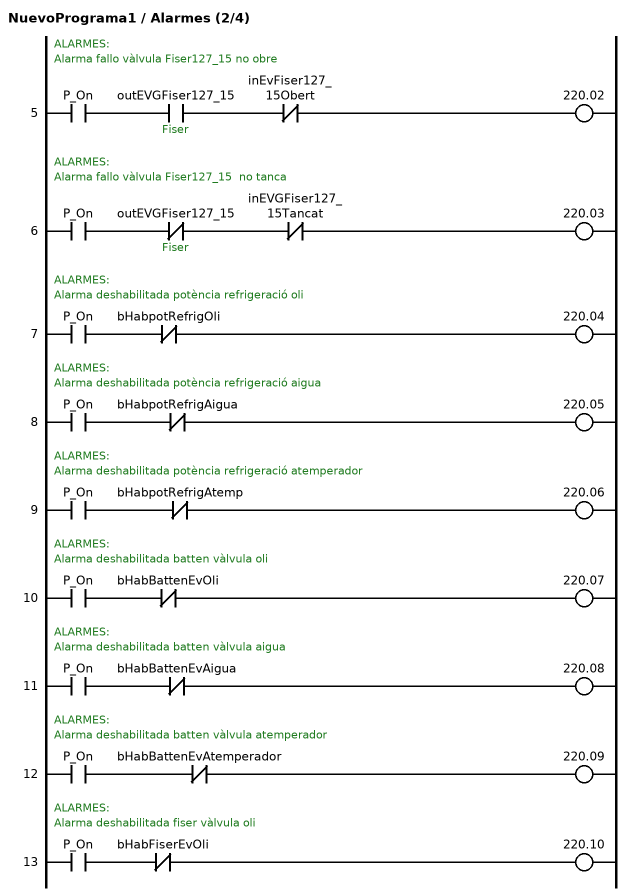
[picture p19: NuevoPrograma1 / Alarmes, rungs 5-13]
; rung 5: ALARMES: / Alarma fallo vàlvula Fiser127_15 no obre
LD P_On
AND outEVGFiser127_15  ; Fiser
ANDNOT inEvFiser127_15Obert
OUT 220.02
; rung 6: ALARMES: / Alarma fallo vàlvula Fiser127_15  no tanca
LD P_On
ANDNOT outEVGFiser127_15  ; Fiser
ANDNOT inEVGFiser127_15Tancat
OUT 220.03
; rung 7: ALARMES: / Alarma deshabilitada potència refrigeració oli
LD P_On
ANDNOT bHabpotRefrigOli
OUT 220.04
; rung 8: ALARMES: / Alarma deshabilitada potència refrigeració aigua
LD P_On
ANDNOT bHabpotRefrigAigua
OUT 220.05
; rung 9: ALARMES: / Alarma deshabilitada potència refrigeració atemperador
LD P_On
ANDNOT bHabpotRefrigAtemp
OUT 220.06
; rung 10: ALARMES: / Alarma deshabilitada batten vàlvula oli
LD P_On
ANDNOT bHabBattenEvOli
OUT 220.07
; rung 11: ALARMES: / Alarma deshabilitada batten vàlvula aigua
LD P_On
ANDNOT bHabBattenEvAigua
OUT 220.08
; rung 12: ALARMES: / Alarma deshabilitada batten vàlvula atemperador
LD P_On
ANDNOT bHabBattenEvAtemperador
OUT 220.09
; rung 13: ALARMES: / Alarma deshabilitada fiser vàlvula oli
LD P_On
ANDNOT bHabFiserEvOli
OUT 220.10

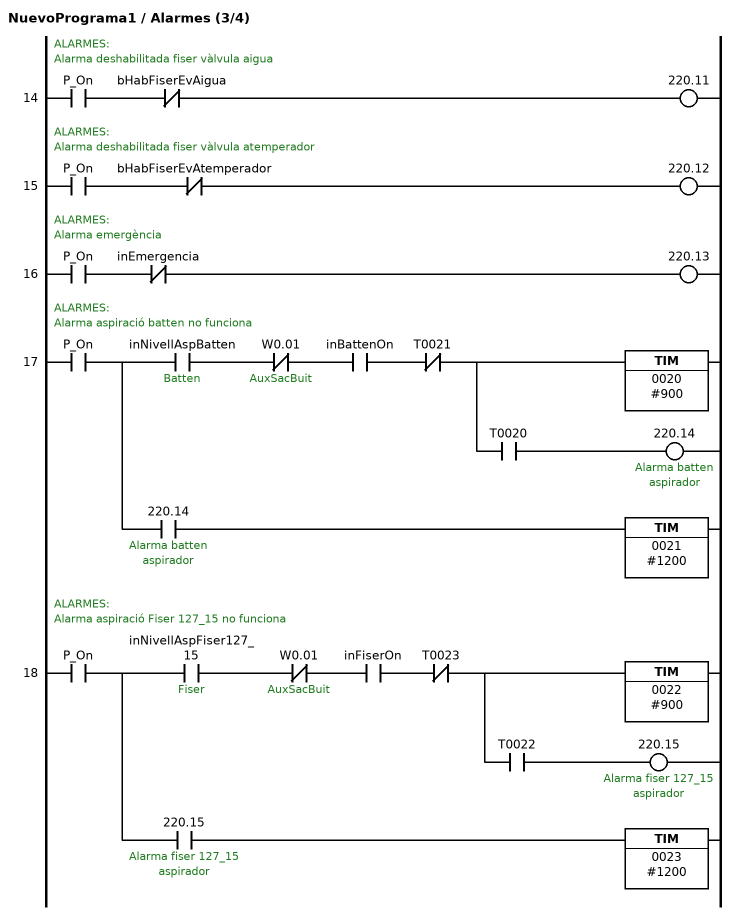
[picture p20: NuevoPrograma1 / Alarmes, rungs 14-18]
; rung 14: ALARMES: / Alarma deshabilitada fiser vàlvula aigua
LD P_On
ANDNOT bHabFiserEvAigua
OUT 220.11
; rung 15: ALARMES: / Alarma deshabilitada fiser vàlvula atemperador
LD P_On
ANDNOT bHabFiserEvAtemperador
OUT 220.12
; rung 16: ALARMES: / Alarma emergència
LD P_On
ANDNOT inEmergencia
OUT 220.13
; rung 17: ALARMES: / Alarma aspiració batten no funciona
LD P_On
OUT TR0
AND inNivellAspBatten  ; Batten
ANDNOT W0.01  ; AuxSacBuit
AND inBattenOn
ANDNOT T0021
TIM 0020 #900
AND T0020
OUT 220.14  ; Alarma batten aspirador
LD TR0
AND 220.14  ; Alarma batten aspirador
TIM 0021 #1200
; rung 18: ALARMES: / Alarma aspiració Fiser 127_15 no funciona
LD P_On
OUT TR0
AND inNivellAspFiser127_15  ; Fiser
ANDNOT W0.01  ; AuxSacBuit
AND inFiserOn
ANDNOT T0023
TIM 0022 #900
AND T0022
OUT 220.15  ; Alarma fiser 127_15 aspirador
LD TR0
AND 220.15  ; Alarma fiser 127_15 aspirador
TIM 0023 #1200

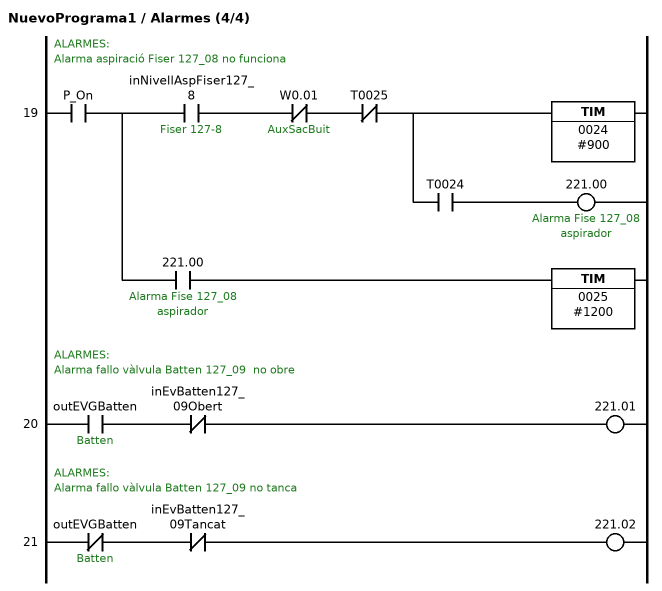
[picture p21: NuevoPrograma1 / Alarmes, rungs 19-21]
; rung 19: ALARMES: / Alarma aspiració Fiser 127_08 no funciona
LD P_On
OUT TR0
AND inNivellAspFiser127_8  ; Fiser 127-8
ANDNOT W0.01  ; AuxSacBuit
ANDNOT T0025
TIM 0024 #900
AND T0024
OUT 221.00  ; Alarma Fise 127_08 aspirador
LD TR0
AND 221.00  ; Alarma Fise 127_08 aspirador
TIM 0025 #1200
; rung 20: ALARMES: / Alarma fallo vàlvula Batten 127_09  no obre
LD outEVGBatten  ; Batten
ANDNOT inEvBatten127_09Obert
OUT 221.01
; rung 21: ALARMES: / Alarma fallo vàlvula Batten 127_09 no tanca
LDNOT outEVGBatten  ; Batten
ANDNOT inEvBatten127_09Tancat
OUT 221.02

### Section PantEmergen

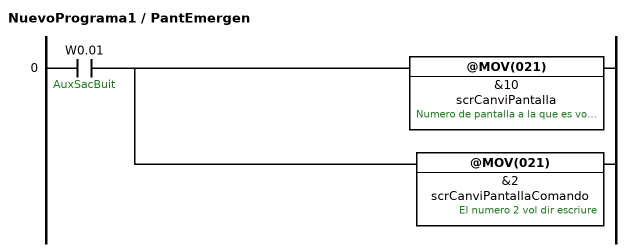
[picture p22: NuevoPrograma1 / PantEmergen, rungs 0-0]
; rung 0
LD W0.01  ; AuxSacBuit
@MOV(021) &10 scrCanviPantalla  ; Numero de pantalla a la que es vol anar
@MOV(021) &2 scrCanviPantallaComando  ; El numero 2 vol dir escriure

### Section END
; rung 0
END(001)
